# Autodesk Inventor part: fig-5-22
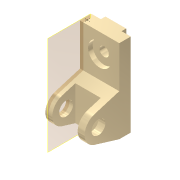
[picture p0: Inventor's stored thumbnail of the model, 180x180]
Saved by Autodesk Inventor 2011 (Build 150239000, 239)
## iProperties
Shininess: 65.0
Angle Display Precision: 2
Document Length Units: 11269
Document Angle Units: 11279
Document Time Units: 11290
Document Mass Units: 11283
Document Length Units Precision: 3
Document Angle Units Precision: 2
Compacted: False
Created: 2001-11
Part Number: fig-5-22
Document SubType Name: Modeling
Designer: Renu Muthoo
Density: 1 g/cm^3
Density: 0.0
Volumn: 0.0
Area: 0.0
PropertySet Name: Model Information
Control State: 0
Master: False
Checked Out: False
Author: Renu Muthoo
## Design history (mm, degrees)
node "Sketch1"
sketch "Sketch2"
  geometry: L1 (33.257, 104.664)-(33.257, -75.336); L2 (33.257, -75.336)-(8.257, -75.336); L3 (8.257, -75.336)-(-45.451, -59.045); L4 (-45.451, -1.628)-(8.257, 14.664); L5 (8.257, 14.664)-(8.257, 104.664); L6 (8.257, 104.664)-(33.257, 104.664); C1 r 15 at (-36.743, -30.336); A1 r 30 centre (-36.743, -30.336) between (-45.451, -1.628) and (-45.451, -59.045)
  constraints: 12 end point, 2 centre point, 2 equal length, 2 parallel, 2 point on circle, 2 tangent, 1 coincident, 1 perpendicular, 1 vertical
  dimensions: "d0" = 180 distance of L1.start L1.end; "d1" = 30 radius of A1; "d2" = 25 distance of L5.end L1.start; "d3" = 45 distance from line of L2 A1.centre; "d4" = 70 distance from line of L1 A1.centre; "d5" = 30 diameter of C1
extrude "Extrusion1" new body sketch "Sketch2" distance "d6" = 85; taper "d7" = 0 deg
workplane "Work Plane1"
sketch "Sketch3"
  geometry: L1 (15, 62.364)-(70, 62.364); L2 (70, 62.364)-(70, -52.386); L3 (70, -52.386)-(15, -52.386); L4 (15, -52.386)-(15, 62.364); L5 (0, -45)-(0, -28.708) reference
  constraints: 8 end point, 2 parallel, 1 horizontal, 1 perpendicular
  dimensions: "d8" = 55 distance of L1.start L1.end; "d9" = 15 distance between parallel lines of L5 L4
extrude "Extrusion2" cut sketch "Sketch3" distance "d10" = 50; taper "d11" = 0 deg
sketch "Sketch4"
  geometry: L1 (0, 25)-(85, 25) reference; L2 (0, 0)-(0, 25) reference; L3 (20, 25)-(65, 25); L4 (65, 25)-(65, 35); L5 (65, 35)-(20, 35); L6 (20, 35)-(20, 25)
  constraints: 8 end point, 2 parallel, 1 horizontal, 1 perpendicular, 1 point on line
  dimensions: "d12" = 45 distance of L4.end L5.end; "d13" = 10 distance of L3.end L4.end; "d14" = 20 distance between parallel lines of L2 L6
extrude "Extrusion3" join sketch "Sketch4" stored distance "d15" = 50; taper "d16" = 0 deg
sketch "Sketch5"
  geometry: L1 (85, 0)-(85, 90) reference; L2 (0, 90)-(85, 90) reference; 1 further point
  dimensions: "d17" = 42 distance from line of L2 point (42.5, 48); "d18" = 42.5 distance from line of L1 point (42.5, 48)
hole "Hole1" sketch "Sketch5" at (42.5, 48) diameter "d19" = 20; stored, may be unused: countersink angle "d23" = 82 deg, drill point angle "d25" = 118 deg; dims "d20" = 6, "d21" = 50, "d22" = 10, "d24" = 8
sketch "Sketch11"
  geometry: 1 further point
workplane "Work Plane17"
body "Solid1"
